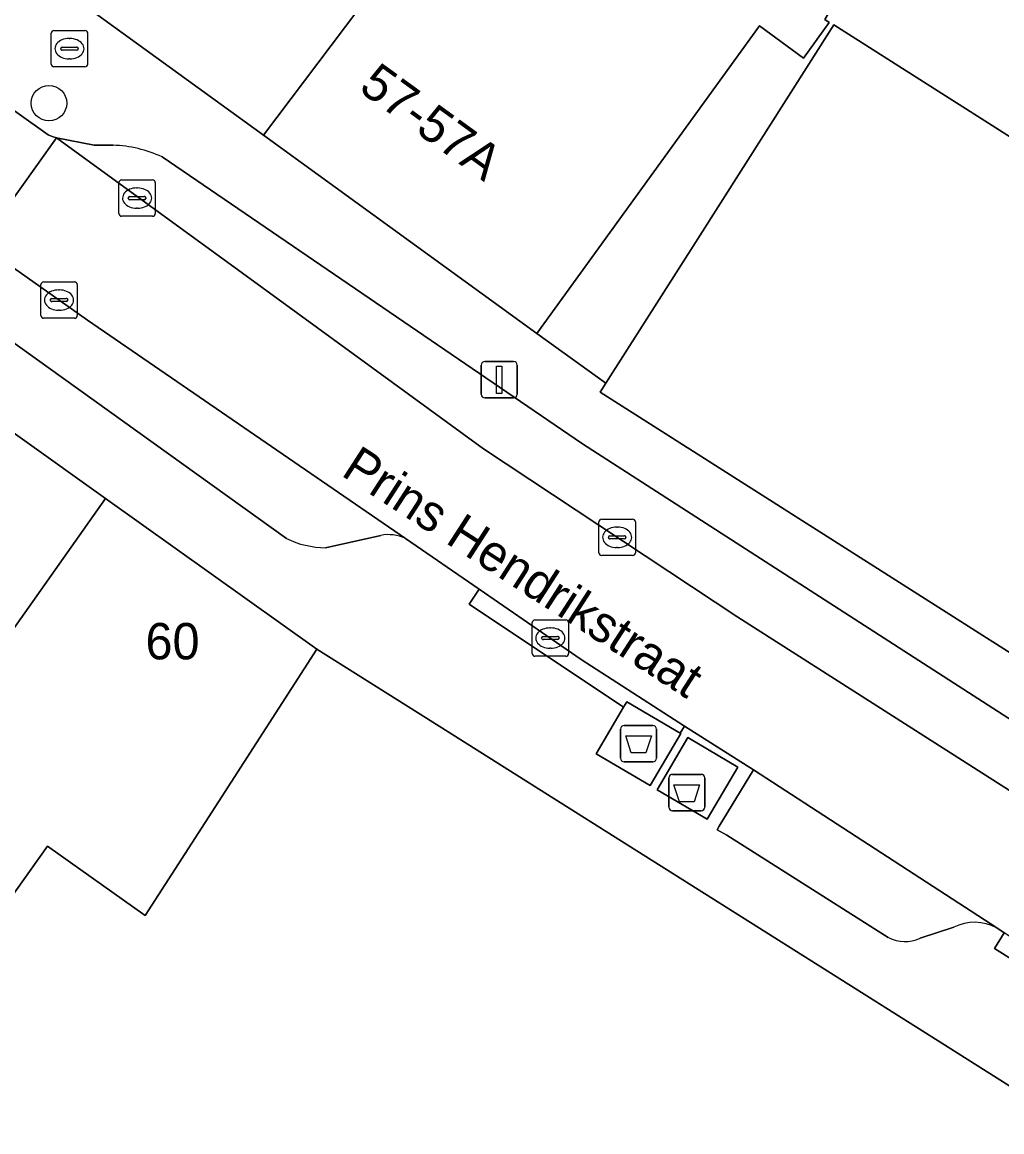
# Model space of a CAD drawing. Extents: x 160663 to 161506, y 382245 to 383291.
# Drawn here: x 161011.08 to 161038.03, y 383026.32 to 383056.85 of the extents above; entities that cross this region are included whole.
import ezdxf

# ---------------------------------------------------------------- set-up
doc = ezdxf.new("R2010")
doc.units = 0
for name, color, linetype in [('IMGEO_Afval_apart_plaats', 7, 'Continuous'), ('IMGEO_Boom', 7, 'Continuous'), ('IMGEO_Brandkraan', 7, 'Continuous'), ('IMGEO_Erf', 7, 'Continuous'), ('IMGEO_Kolk', 7, 'Continuous'), ('IMGEO_Lichtmast', 7, 'Continuous'), ('IMGEO_Muur', 7, 'Continuous'), ('IMGEO_Openbare_ruimte_label', 7, 'Continuous'), ('IMGEO_Pand', 7, 'Continuous'), ('IMGEO_Pand_nummerreeks', 7, 'Continuous'), ('IMGEO_Parkeervlak_open', 7, 'Continuous'), ('IMGEO_Rijbaan_lokaal_open', 7, 'Continuous'), ('IMGEO_Voetpad_gesloten', 7, 'Continuous'), ('IMGEO_Voetpad_open', 7, 'Continuous')]:
    doc.layers.add(name, color=color, linetype=linetype)

msp = doc.modelspace()

# ---------------------------------------------------------------- linework, layer by layer
at = {"layer": 'IMGEO_Afval_apart_plaats'}
for p, q in [((161027.541, 383036.597), (161027.541, 383037.397)), ((161027.541, 383037.397), (161027.541, 383036.597)), ((161027.641, 383037.497), (161028.431, 383037.497)), ((161028.431, 383037.497), (161027.641, 383037.497)), ((161028.531, 383037.397), (161028.531, 383036.597)), ((161028.531, 383036.597), (161028.531, 383037.397)), ((161028.431, 383036.497), (161027.641, 383036.497)), ((161027.641, 383036.497), (161028.431, 383036.497)), ((161028.868, 383035.253), (161028.868, 383036.053)), ((161028.868, 383036.053), (161028.868, 383035.253)), ((161028.968, 383036.153), (161029.758, 383036.153)), ((161029.758, 383036.153), (161028.968, 383036.153)), ((161029.858, 383036.053), (161029.858, 383035.253)), ((161029.858, 383035.253), (161029.858, 383036.053)), ((161029.758, 383035.153), (161028.968, 383035.153)), ((161028.968, 383035.153), (161029.758, 383035.153))]:
    msp.add_line(p, q, dxfattribs=at)
for points in [[(161027.684, 383037.211), (161028.388, 383037.211), (161028.239, 383036.741), (161027.833, 383036.741), (161027.684, 383037.211)], [(161029.011, 383035.867), (161029.715, 383035.867), (161029.566, 383035.397), (161029.16, 383035.397), (161029.011, 383035.867)]]:
    msp.add_lwpolyline(points, dxfattribs=at)
for centre, start, end in [((161027.641, 383037.397), 90, 180), ((161027.641, 383037.397), 90, 180), ((161028.431, 383037.397), 0, 90), ((161028.431, 383037.397), 360, 90), ((161027.641, 383036.597), 180, 270), ((161027.641, 383036.597), 180, 270), ((161028.431, 383036.597), 270, 0), ((161028.431, 383036.597), 270, 0), ((161028.968, 383036.053), 90, 180), ((161028.968, 383036.053), 90, 180), ((161029.758, 383036.053), 0, 90), ((161029.758, 383036.053), 360, 90), ((161028.968, 383035.253), 180, 270), ((161028.968, 383035.253), 180, 270), ((161029.758, 383035.253), 270, 0), ((161029.758, 383035.253), 270, 0)]:
    msp.add_arc(centre, 0.1, start, end, dxfattribs=at)
at = {"layer": 'IMGEO_Boom'}
msp.add_circle((161011.813, 383054.621), 0.489, dxfattribs=at)
at = {"layer": 'IMGEO_Brandkraan'}
for p, q in [((161011.952, 383056.621), (161012.804, 383056.621)), ((161011.877, 383055.695), (161011.877, 383056.547)), ((161012.365, 383056.401), (161012.39, 383056.401)), ((161012.878, 383056.547), (161012.878, 383055.695)), ((161012.136, 383056.115), (161012.136, 383056.127)), ((161012.574, 383056.078), (161012.176, 383056.078)), ((161012.179, 383056.164), (161012.577, 383056.164)), ((161012.62, 383056.127), (161012.62, 383056.115)), ((161012.388, 383055.841), (161012.363, 383055.841)), ((161012.804, 383055.621), (161011.952, 383055.621))]:
    msp.add_line(p, q, dxfattribs=at)
for points in [[(161011.952, 383056.621), (161012.804, 383056.621)], [(161011.877, 383055.695), (161011.877, 383056.547)], [(161012.878, 383056.547), (161012.878, 383055.695)], [(161012.804, 383055.621), (161011.952, 383055.621)]]:
    msp.add_lwpolyline(points, dxfattribs=at)
for centre, radius, start, end in [((161011.954, 383056.545), 0.0765, 91.552, 178.448), ((161011.954, 383056.545), 0.0765, 91.552, 178.448), ((161012.802, 383056.545), 0.0765, 1.552, 88.448), ((161012.802, 383056.545), 0.0765, 1.552, 88.448), ((161012.176, 383056.124), 0.0403, 85.8775, 175.7526), ((161012.173, 383056.114), 0.0366, 178.938, 274.7102), ((161012.577, 383056.121), 0.043, 264.8664, 352.4533), ((161012.581, 383056.126), 0.0386, 1.7309, 96.639), ((161011.954, 383055.697), 0.0765, 181.552, 268.448), ((161011.954, 383055.697), 0.0765, 181.552, 268.448), ((161012.802, 383055.697), 0.0765, 271.552, 358.448), ((161012.802, 383055.697), 0.0765, 271.552, 358.448)]:
    msp.add_arc(centre, radius, start, end, dxfattribs=at)
for centre, major_axis, ratio, start_param, end_param in [((161012.364, 383056.121), (-0.387, 0.002), 0.722429, 4.712389, 7.853982), ((161012.389, 383056.121), (-0.39, 0.002), 0.717154, 1.570796, 4.712389)]:
    msp.add_ellipse(centre, major_axis=major_axis, ratio=ratio, start_param=start_param, end_param=end_param, dxfattribs=at)
at = {"layer": 'IMGEO_Erf'}
for points in [[(161029.876, 383062.184), (161027.911, 383059.467), (161029.085, 383058.618), (161033.964, 383067.181), (161037.886, 383064.946), (161033.159, 383056.928), (161033.282, 383056.839), (161032.578, 383055.865), (161031.36, 383056.746), (161025.238, 383048.281), (161027.134, 383046.913), (161029.664, 383050.891), (161033.411, 383056.782), (161048.444, 383047.224)], [(161039.5, 383026.785), (161036.108, 383028.925), (161025.283, 383035.755), (161021.951, 383037.858), (161019.187, 383039.602), (161016.476, 383035.398), (161014.456, 383032.264), (161011.776, 383034.175), (161008.461, 383029.525), (161005.851, 383031.386), (161005.162, 383030.419), (161004.845, 383030.645), (161004.379, 383030.977), (161005.048, 383031.915), (161002.538, 383033.705), (161003.69, 383035.322), (161001.37, 383036.964), (161000.513, 383037.571), (161000, 383037.934), (160998.137, 383039.253), (161000, 383041.883), (161000, 383042.006), (160998.501, 383043.067), (160996.869, 383040.763)]]:
    msp.add_lwpolyline(points, dxfattribs=at)
at = {"layer": 'IMGEO_Kolk'}
for p, q in [((161013.738, 383051.583), (161013.738, 383052.435)), ((161013.813, 383052.509), (161014.665, 383052.509)), ((161014.739, 383052.435), (161014.739, 383051.583)), ((161014.04, 383052.052), (161014.438, 383052.052)), ((161014.226, 383052.289), (161014.251, 383052.289)), ((161013.997, 383052.003), (161013.997, 383052.015)), ((161014.435, 383051.966), (161014.037, 383051.966)), ((161014.249, 383051.729), (161014.224, 383051.729)), ((161014.481, 383052.015), (161014.481, 383052.003)), ((161014.665, 383051.509), (161013.813, 383051.509)), ((161011.59, 383048.777), (161011.59, 383049.629)), ((161011.665, 383049.703), (161012.517, 383049.703)), ((161012.591, 383049.629), (161012.591, 383048.777)), ((161012.078, 383049.483), (161012.103, 383049.483)), ((161011.849, 383049.197), (161011.849, 383049.209)), ((161012.287, 383049.16), (161011.889, 383049.16)), ((161011.892, 383049.246), (161012.29, 383049.246)), ((161012.333, 383049.209), (161012.333, 383049.197)), ((161012.517, 383048.703), (161011.665, 383048.703)), ((161012.101, 383048.923), (161012.076, 383048.923)), ((161026.947, 383042.249), (161026.947, 383043.101)), ((161027.022, 383043.175), (161027.874, 383043.175)), ((161027.435, 383042.955), (161027.46, 383042.955)), ((161027.948, 383043.101), (161027.948, 383042.249)), ((161027.206, 383042.669), (161027.206, 383042.681)), ((161027.644, 383042.632), (161027.246, 383042.632)), ((161027.249, 383042.718), (161027.647, 383042.718)), ((161027.69, 383042.681), (161027.69, 383042.669)), ((161027.458, 383042.395), (161027.433, 383042.395)), ((161027.874, 383042.175), (161027.022, 383042.175)), ((161025.109, 383039.476), (161025.109, 383040.328)), ((161025.184, 383040.402), (161026.036, 383040.402)), ((161025.597, 383040.182), (161025.622, 383040.182)), ((161026.11, 383040.328), (161026.11, 383039.476)), ((161025.368, 383039.896), (161025.368, 383039.908)), ((161025.806, 383039.859), (161025.408, 383039.859)), ((161025.411, 383039.945), (161025.809, 383039.945)), ((161025.852, 383039.908), (161025.852, 383039.896)), ((161025.62, 383039.622), (161025.595, 383039.622)), ((161026.036, 383039.402), (161025.184, 383039.402))]:
    msp.add_line(p, q, dxfattribs=at)
for points in [[(161013.738, 383051.583), (161013.738, 383052.435)], [(161013.813, 383052.509), (161014.665, 383052.509)], [(161014.739, 383052.435), (161014.739, 383051.583)], [(161014.665, 383051.509), (161013.813, 383051.509)], [(161011.59, 383048.777), (161011.59, 383049.629)], [(161011.665, 383049.703), (161012.517, 383049.703)], [(161012.591, 383049.629), (161012.591, 383048.777)], [(161012.517, 383048.703), (161011.665, 383048.703)], [(161026.947, 383042.249), (161026.947, 383043.101)], [(161027.022, 383043.175), (161027.874, 383043.175)], [(161027.948, 383043.101), (161027.948, 383042.249)], [(161027.874, 383042.175), (161027.022, 383042.175)], [(161025.109, 383039.476), (161025.109, 383040.328)], [(161025.184, 383040.402), (161026.036, 383040.402)], [(161026.11, 383040.328), (161026.11, 383039.476)], [(161026.036, 383039.402), (161025.184, 383039.402)]]:
    msp.add_lwpolyline(points, dxfattribs=at)
for centre, radius, start, end in [((161013.815, 383052.433), 0.0765, 91.552, 178.448), ((161013.815, 383052.433), 0.0765, 91.552, 178.448), ((161014.663, 383052.433), 0.0765, 1.552, 88.448), ((161014.663, 383052.433), 0.0765, 1.552, 88.448), ((161014.037, 383052.012), 0.0403, 85.8775, 175.7526), ((161014.442, 383052.014), 0.0386, 1.7309, 96.639), ((161014.034, 383052.002), 0.0366, 178.938, 274.7102), ((161014.438, 383052.009), 0.043, 264.8664, 352.4533), ((161013.815, 383051.585), 0.0765, 181.552, 268.448), ((161013.815, 383051.585), 0.0765, 181.552, 268.448), ((161014.663, 383051.585), 0.0765, 271.552, 358.448), ((161014.663, 383051.585), 0.0765, 271.552, 358.448), ((161011.667, 383049.627), 0.0765, 91.552, 178.448), ((161011.667, 383049.627), 0.0765, 91.552, 178.448), ((161012.515, 383049.627), 0.0765, 1.552, 88.448), ((161012.515, 383049.627), 0.0765, 1.552, 88.448), ((161011.889, 383049.206), 0.0403, 85.8775, 175.7526), ((161011.886, 383049.196), 0.0366, 178.938, 274.7102), ((161012.29, 383049.203), 0.043, 264.8664, 352.4533), ((161012.294, 383049.208), 0.0386, 1.7309, 96.639), ((161011.667, 383048.779), 0.0765, 181.552, 268.448), ((161011.667, 383048.779), 0.0765, 181.552, 268.448), ((161012.515, 383048.779), 0.0765, 271.552, 358.448), ((161012.515, 383048.779), 0.0765, 271.552, 358.448), ((161027.024, 383043.099), 0.0765, 91.552, 178.448), ((161027.024, 383043.099), 0.0765, 91.552, 178.448), ((161027.872, 383043.099), 0.0765, 1.552, 88.448), ((161027.872, 383043.099), 0.0765, 1.552, 88.448), ((161027.246, 383042.678), 0.0403, 85.8775, 175.7526), ((161027.243, 383042.668), 0.0366, 178.938, 274.7102), ((161027.647, 383042.675), 0.043, 264.8664, 352.4533), ((161027.651, 383042.68), 0.0386, 1.7309, 96.639), ((161027.024, 383042.251), 0.0765, 181.552, 268.448), ((161027.024, 383042.251), 0.0765, 181.552, 268.448), ((161027.872, 383042.251), 0.0765, 271.552, 358.448), ((161027.872, 383042.251), 0.0765, 271.552, 358.448), ((161025.186, 383040.326), 0.0765, 91.552, 178.448), ((161025.186, 383040.326), 0.0765, 91.552, 178.448), ((161026.034, 383040.326), 0.0765, 1.552, 88.448), ((161026.034, 383040.326), 0.0765, 1.552, 88.448), ((161025.408, 383039.905), 0.0403, 85.8775, 175.7526), ((161025.405, 383039.895), 0.0366, 178.938, 274.7102), ((161025.809, 383039.902), 0.043, 264.8664, 352.4533), ((161025.813, 383039.907), 0.0386, 1.7309, 96.639), ((161025.186, 383039.478), 0.0765, 181.552, 268.448), ((161025.186, 383039.478), 0.0765, 181.552, 268.448), ((161026.034, 383039.478), 0.0765, 271.552, 358.448), ((161026.034, 383039.478), 0.0765, 271.552, 358.448)]:
    msp.add_arc(centre, radius, start, end, dxfattribs=at)
for centre, major_axis, ratio, start_param, end_param in [((161014.225, 383052.009), (-0.387, 0.002), 0.722429, 4.712389, 7.853982), ((161014.25, 383052.009), (-0.39, 0.002), 0.717154, 1.570796, 4.712389), ((161012.077, 383049.203), (-0.387, 0.002), 0.722429, 4.712389, 7.853982), ((161012.102, 383049.203), (-0.39, 0.002), 0.717154, 1.570796, 4.712389), ((161027.434, 383042.675), (-0.387, 0.002), 0.722429, 4.712389, 7.853982), ((161027.459, 383042.675), (-0.39, 0.002), 0.717154, 1.570796, 4.712389), ((161025.596, 383039.902), (-0.387, 0.002), 0.722429, 4.712389, 7.853982), ((161025.621, 383039.902), (-0.39, 0.002), 0.717154, 1.570796, 4.712389)]:
    msp.add_ellipse(centre, major_axis=major_axis, ratio=ratio, start_param=start_param, end_param=end_param, dxfattribs=at)
at = {"layer": 'IMGEO_Lichtmast'}
for p, q in [((161023.808, 383047.511), (161024.598, 383047.511)), ((161024.598, 383047.511), (161023.808, 383047.511)), ((161023.708, 383046.611), (161023.708, 383047.411)), ((161023.708, 383047.411), (161023.708, 383046.611)), ((161024.698, 383047.411), (161024.698, 383046.611)), ((161024.698, 383046.611), (161024.698, 383047.411)), ((161024.598, 383046.511), (161023.808, 383046.511)), ((161023.808, 383046.511), (161024.598, 383046.511))]:
    msp.add_line(p, q, dxfattribs=at)
msp.add_lwpolyline([(161024.128, 383047.386), (161024.278, 383047.386), (161024.278, 383046.636), (161024.128, 383046.636), (161024.128, 383047.386)], dxfattribs=at)
for centre, start, end in [((161023.808, 383047.411), 90, 180), ((161023.808, 383047.411), 90, 180), ((161024.598, 383047.411), 0, 90), ((161024.598, 383047.411), 360, 90), ((161023.808, 383046.611), 180, 270), ((161023.808, 383046.611), 180, 270), ((161024.598, 383046.611), 270, 0), ((161024.598, 383046.611), 270, 0)]:
    msp.add_arc(centre, 0.1, start, end, dxfattribs=at)
at = {"layer": 'IMGEO_Muur'}
for points in [[(161019.187, 383039.602), (161021.951, 383037.858)], [(161025.283, 383035.755), (161036.108, 383028.925)]]:
    msp.add_lwpolyline(points, dxfattribs=at)
at = {"layer": 'IMGEO_Pand'}
for points in [[(161026.317, 383065.155), (161027.322, 383066.488), (161024.824, 383068.295), (161021.947, 383064.317), (161022.349, 383064.027), (161021.592, 383062.98), (161020.665, 383063.65), (161021.284, 383064.506), (161021.181, 383065.146), (161018.019, 383067.433), (161011.26, 383058.428), (161017.714, 383053.743)], [(161048.444, 383047.224), (161033.411, 383056.782), (161029.664, 383050.891), (161027.134, 383046.913), (161026.98, 383046.672), (161048.411, 383033.039), (161049.305, 383032.471), (161050.201, 383033.88), (161052.358, 383032.519), (161051.456, 383031.102), (161061.89, 383024.465), (161068.328, 383034.587), (161063.216, 383037.832)], [(161008.601, 383047.148), (161001.37, 383036.964), (161003.69, 383035.322), (161002.538, 383033.705), (161005.048, 383031.915), (161008.293, 383036.357), (161008.196, 383036.426), (161013.371, 383043.748)], [(161005.048, 383031.915), (161004.379, 383030.977), (161004.845, 383030.645), (161005.162, 383030.419), (161005.851, 383031.386), (161008.461, 383029.525), (161011.776, 383034.175), (161014.456, 383032.264), (161016.476, 383035.398), (161019.187, 383039.602), (161013.371, 383043.748), (161008.196, 383036.426), (161008.293, 383036.357)]]:
    msp.add_lwpolyline(points, close=True, dxfattribs=at)
msp.add_lwpolyline([(161028.172, 383065.601), (161026.317, 383065.155), (161017.714, 383053.743), (161025.238, 383048.281), (161031.36, 383056.746), (161032.578, 383055.865), (161033.282, 383056.839), (161033.159, 383056.928), (161037.886, 383064.946)], dxfattribs=at)
at = {"layer": 'IMGEO_Parkeervlak_open'}
for points in [[(160999.215, 383056.323), (161000, 383055.808), (161018.351, 383042.641)], [(161013.579, 383053.465), (161013.058, 383053.465), (161012.017, 383053.67), (161017.137, 383049.948), (161023.767, 383045.113), (161030.766, 383040.479), (161039.174, 383035.116), (161047.653, 383029.663), (161056.443, 383024.051), (161060.074, 383021.752)], [(161059.441, 383023.143), (161059.314, 383023.651), (161058.871, 383024.388), (161026.498, 383045.25), (161014.924, 383053.146)], [(161021.62, 383042.643), (161012.871, 383048.655), (161009.922, 383050.733)], [(161019.421, 383042.388), (161020.943, 383042.728)], [(161031.195, 383036.275), (161030.258, 383034.723), (161030.201, 383034.629), (161030.461, 383034.476), (161034.909, 383031.662)], [(161037.89, 383031.927), (161031.195, 383036.275)], [(161035.784, 383031.642), (161036.709, 383031.945)]]:
    msp.add_lwpolyline(points, dxfattribs=at)
for centre, radius, start, end in [((161013.464, 383049.983), 3.483, 65.2133, 88.1015), ((161019.45, 383044.899), 2.511, 244.0497, 269.3439), ((161021.153, 383041.663), 1.086, 64.5335, 101.1539), ((161037.282, 383030.815), 1.267, 61.3505, 116.9031), ((161035.367, 383032.539), 0.989, 242.4423, 294.9389)]:
    msp.add_arc(centre, radius, start, end, dxfattribs=at)
at = {"layer": 'IMGEO_Rijbaan_lokaal_open'}
msp.add_lwpolyline([(161012.017, 383053.67), (161011.903, 383053.709), (161011.79, 383053.75), (161009.257, 383055.551), (161008.196, 383056.32), (161006.105, 383053.424), (161009.922, 383050.733)], close=True, dxfattribs=at)
msp.add_lwpolyline([(161039.174, 383035.116), (161030.766, 383040.479), (161023.767, 383045.113), (161017.137, 383049.948), (161012.017, 383053.67), (161009.922, 383050.733), (161012.871, 383048.655), (161021.62, 383042.643), (161023.653, 383041.246), (161026.46, 383039.316), (161029.303, 383037.478), (161031.195, 383036.275), (161037.89, 383031.927), (161038.093, 383031.787)], dxfattribs=at)
at = {"layer": 'IMGEO_Voetpad_gesloten'}
for points in [[(161029.202, 383037.276), (161029.178, 383037.29), (161027.714, 383038.152), (161027.623, 383037.998), (161026.87, 383036.718), (161028.358, 383035.842)], [(161029.928, 383034.918), (161030.772, 383036.352), (161029.394, 383037.163), (161028.55, 383035.729)]]:
    msp.add_lwpolyline(points, close=True, dxfattribs=at)
at = {"layer": 'IMGEO_Voetpad_open'}
for points in [[(160955.867, 383086.614), (160959.764, 383083.167), (160963.718, 383079.83), (160969.386, 383075.048), (160972.425, 383072.884), (160975.614, 383070.613), (160976.345, 383070.055), (160981.723, 383066.24), (160981.925, 383066.097), (160984.383, 383064.359), (160989.497, 383060.735), (161000, 383053.292), (161000.047, 383053.259), (161007.755, 383047.797), (161008.601, 383047.148), (161013.371, 383043.748), (161019.187, 383039.602), (161021.951, 383037.858), (161025.283, 383035.755), (161036.108, 383028.925), (161039.5, 383026.785)], [(161060.074, 383021.752), (161060.814, 383021.283), (161061.522, 383020.835), (161063.032, 383019.896), (161064.782, 383019.236), (161066.34, 383021.634), (161061.89, 383024.465), (161051.456, 383031.102), (161049.305, 383032.471), (161048.411, 383033.039), (161026.98, 383046.672), (161027.134, 383046.913), (161025.238, 383048.281), (161017.714, 383053.743), (161011.26, 383058.428)], [(161006.749, 383057.368), (161008.196, 383056.32), (161009.257, 383055.551), (161011.79, 383053.75), (161011.903, 383053.709), (161012.017, 383053.67), (161013.058, 383053.465), (161013.579, 383053.465)], [(161018.351, 383042.641), (161000, 383055.808), (160999.215, 383056.323)], [(161014.924, 383053.146), (161026.498, 383045.25), (161058.871, 383024.388), (161059.314, 383023.651), (161059.441, 383023.143)], [(161020.943, 383042.728), (161019.421, 383042.388)], [(161034.909, 383031.662), (161030.461, 383034.476), (161030.201, 383034.629), (161030.258, 383034.723), (161031.195, 383036.275), (161029.303, 383037.478), (161029.178, 383037.29), (161029.202, 383037.276), (161028.358, 383035.842), (161026.87, 383036.718), (161027.623, 383037.998), (161023.373, 383040.832), (161023.653, 383041.246), (161021.62, 383042.643)], [(161036.709, 383031.945), (161035.784, 383031.642)], [(161043.475, 383028.393), (161043.259, 383028.541), (161042.993, 383028.118), (161037.827, 383031.364), (161038.093, 383031.787), (161037.89, 383031.927)]]:
    msp.add_lwpolyline(points, dxfattribs=at)
for points in [[(161029.178, 383037.29), (161029.303, 383037.478), (161026.46, 383039.316), (161023.653, 383041.246), (161023.373, 383040.832), (161027.623, 383037.998), (161027.714, 383038.152)], [(161030.772, 383036.352), (161029.928, 383034.918), (161028.55, 383035.729), (161029.394, 383037.163)], [(161038.093, 383031.787), (161037.827, 383031.364), (161042.993, 383028.118), (161043.259, 383028.541), (161040.038, 383030.538)]]:
    msp.add_lwpolyline(points, close=True, dxfattribs=at)
for centre, radius, start, end in [((161013.464, 383049.983), 3.483, 65.2133, 88.1015), ((161019.45, 383044.899), 2.511, 244.0497, 269.3439), ((161021.153, 383041.663), 1.086, 64.5335, 101.1539), ((161037.282, 383030.815), 1.267, 61.3505, 116.9031), ((161035.367, 383032.539), 0.989, 242.4423, 294.9389)]:
    msp.add_arc(centre, radius, start, end, dxfattribs=at)

# ---------------------------------------------------------------- texts
at = {"layer": 'IMGEO_Openbare_ruimte_label'}
msp.add_text('Prins Hendrikstraat', height=1, rotation=327.1202, dxfattribs=at).set_placement((161019.82, 383044.396))
at = {"layer": 'IMGEO_Pand_nummerreeks'}
msp.add_text('57-57A', height=1, rotation=324.024, dxfattribs=at).set_placement((161020.303, 383054.978))
msp.add_text('60', height=1, dxfattribs=at).set_placement((161014.47, 383039.317))

doc.saveas('drawing.dxf')
